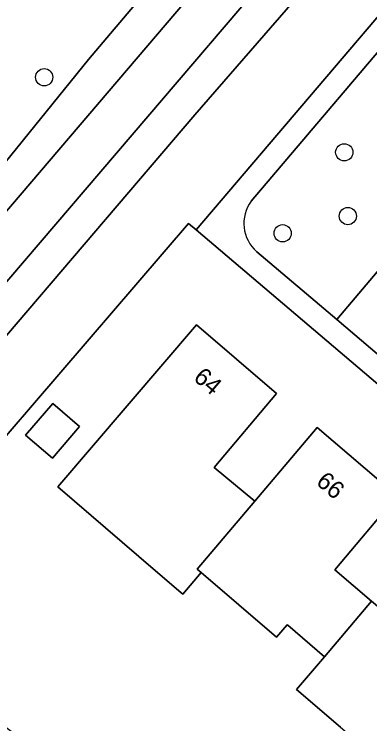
# Model space of a CAD drawing. Extents: x 156412 to 157779, y 382335 to 383768.
# Drawn here: x 156781.32 to 156801.54, y 382429.31 to 382469.61 of the extents above; entities that cross this region are included whole.
import ezdxf

# ---------------------------------------------------------------- set-up
doc = ezdxf.new("R2010")
doc.units = 0
for name, color, linetype in [('IMGEO_Berm_groen', 7, 'Continuous'), ('IMGEO_Boom', 7, 'Continuous'), ('IMGEO_Erf', 7, 'Continuous'), ('IMGEO_Groenvoorziening', 7, 'Continuous'), ('IMGEO_Oever', 7, 'Continuous'), ('IMGEO_Pand', 7, 'Continuous'), ('IMGEO_Pand_nummerreeks', 7, 'Continuous'), ('IMGEO_Parkeervlak_open', 7, 'Continuous'), ('IMGEO_Voetpad_open', 7, 'Continuous'), ('IMGEO_Waterloop', 7, 'Continuous')]:
    doc.layers.add(name, color=color, linetype=linetype)

msp = doc.modelspace()

# ---------------------------------------------------------------- linework, layer by layer
at = {"layer": 'IMGEO_Berm_groen'}
for points in [[(156806.038, 382464.795), (156802.386, 382467.905), (156794.793, 382458.992)], [(156795.115, 382456.117), (156799.666, 382452.263), (156804.586, 382458.056)]]:
    msp.add_lwpolyline(points, dxfattribs=at)
msp.add_arc((156796.52, 382457.73), 2.139, 143.8425, 228.9385, dxfattribs=at)
at = {"layer": 'IMGEO_Boom'}
for centre in [(156783.028, 382466.026), (156800.09, 382461.765), (156800.293, 382458.143), (156796.587, 382457.167)]:
    msp.add_circle(centre, 0.489, dxfattribs=at)
at = {"layer": 'IMGEO_Erf'}
for points in [[(156849.783, 382408.111), (156821.763, 382431.828), (156791.675, 382457.364), (156791.237, 382457.729), (156772.208, 382435.618), (156781.23, 382428.836)], [(156799.87, 382429.132), (156797.367, 382431.255), (156798.968, 382433.123), (156796.887, 382434.907), (156796.85, 382434.939), (156796.239, 382434.225), (156791.957, 382437.897), (156790.909, 382436.674), (156790.691, 382436.861), (156788.408, 382438.819), (156783.803, 382442.767), (156791.692, 382451.968), (156796.235, 382448.073), (156792.687, 382443.876), (156794.997, 382441.95), (156798.545, 382446.146), (156803.106, 382442.264), (156799.551, 382438.056), (156801.645, 382436.286), (156804.14, 382434.178), (156807.696, 382438.387), (156812.265, 382434.503), (156816.834, 382430.618), (156813.267, 382426.411)]]:
    msp.add_lwpolyline(points, dxfattribs=at)
msp.add_lwpolyline([(156781.972, 382445.705), (156783.516, 382447.506), (156785.042, 382446.198), (156783.497, 382444.397)], close=True, dxfattribs=at)
at = {"layer": 'IMGEO_Groenvoorziening'}
for points in [[(156759.817, 382444.931), (156760.299, 382444.569), (156772.208, 382435.618), (156791.237, 382457.729), (156791.675, 382457.364), (156810.572, 382479.519), (156831.533, 382504.167), (156830.605, 382504.95), (156826.003, 382508.837)], [(156820.95, 382498.966), (156818.053, 382495.021), (156800.704, 382474.383), (156791.599, 382463.885), (156773.907, 382443.229)], [(156767.925, 382445.845), (156768.61, 382446.9), (156773.976, 382452.765), (156785.555, 382467.028), (156794.651, 382477.777)]]:
    msp.add_lwpolyline(points, dxfattribs=at)
at = {"layer": 'IMGEO_Oever'}
for points in [[(156816.587, 382502.97), (156813.196, 382499.284), (156794.651, 382477.777), (156785.555, 382467.028), (156773.976, 382452.765), (156768.61, 382446.9), (156767.925, 382445.845)], [(156773.907, 382443.229), (156791.599, 382463.885), (156800.704, 382474.383), (156818.053, 382495.021), (156820.95, 382498.966)]]:
    msp.add_lwpolyline(points, dxfattribs=at)
msp.add_lwpolyline([(156769.56, 382445.166), (156816.396, 382500.028), (156818.52, 382498.415), (156771.428, 382443.383)], close=True, dxfattribs=at)
at = {"layer": 'IMGEO_Pand'}
for points in [[(156796.235, 382448.073), (156791.692, 382451.968), (156783.803, 382442.767), (156788.408, 382438.819), (156790.691, 382436.861), (156790.909, 382436.674), (156791.957, 382437.897), (156791.731, 382438.091), (156794.997, 382441.95), (156792.687, 382443.876)], [(156781.972, 382445.705), (156783.497, 382444.397), (156785.042, 382446.198), (156783.516, 382447.506)], [(156803.106, 382442.264), (156798.545, 382446.146), (156794.997, 382441.95), (156791.731, 382438.091), (156791.957, 382437.897), (156796.239, 382434.225), (156796.85, 382434.939), (156796.887, 382434.907), (156798.968, 382433.123), (156801.645, 382436.286), (156799.551, 382438.056)], [(156812.265, 382434.503), (156807.696, 382438.387), (156804.14, 382434.178), (156801.645, 382436.286), (156798.968, 382433.123), (156797.367, 382431.255), (156799.87, 382429.132), (156804.439, 382425.255)]]:
    msp.add_lwpolyline(points, close=True, dxfattribs=at)
at = {"layer": 'IMGEO_Parkeervlak_open'}
msp.add_lwpolyline([(156804.586, 382458.056), (156799.666, 382452.263), (156802.099, 382450.202), (156805.592, 382454.345)], dxfattribs=at)
at = {"layer": 'IMGEO_Voetpad_open'}
for points in [[(156794.793, 382458.992), (156802.386, 382467.905), (156803.522, 382469.239), (156808.479, 382475.058), (156810.033, 382476.883), (156811.563, 382478.679), (156814.902, 382482.597), (156818.136, 382486.392), (156824.64, 382494.023), (156826.198, 382495.85), (156827.163, 382496.983), (156832.477, 382503.264), (156832.153, 382503.644), (156831.533, 382504.167), (156810.572, 382479.519), (156791.675, 382457.364), (156821.763, 382431.828), (156849.783, 382408.111), (156876.247, 382385.72), (156880.938, 382381.751), (156899.797, 382365.794), (156922.237, 382392.249)], [(156828.869, 382427.532), (156824.929, 382430.869), (156822.632, 382432.815), (156820.341, 382434.755), (156816.404, 382438.089), (156813.213, 382440.791), (156811.181, 382442.512), (156806.596, 382446.395), (156804.578, 382448.103), (156802.099, 382450.202), (156799.666, 382452.263), (156795.115, 382456.117)]]:
    msp.add_lwpolyline(points, dxfattribs=at)
msp.add_arc((156796.52, 382457.73), 2.139, 143.8425, 228.9385, dxfattribs=at)
at = {"layer": 'IMGEO_Waterloop'}
msp.add_lwpolyline([(156769.56, 382445.166), (156771.428, 382443.383), (156818.52, 382498.415), (156816.396, 382500.028)], close=True, dxfattribs=at)

# ---------------------------------------------------------------- texts
at = {"layer": 'IMGEO_Pand_nummerreeks'}
for s, rotation, p in [('64', 319.3888, (156791.456, 382448.878)), ('66', 319.6007, (156798.429, 382442.961))]:
    msp.add_text(s, height=1, rotation=rotation, dxfattribs=at).set_placement(p)

doc.saveas('drawing.dxf')
